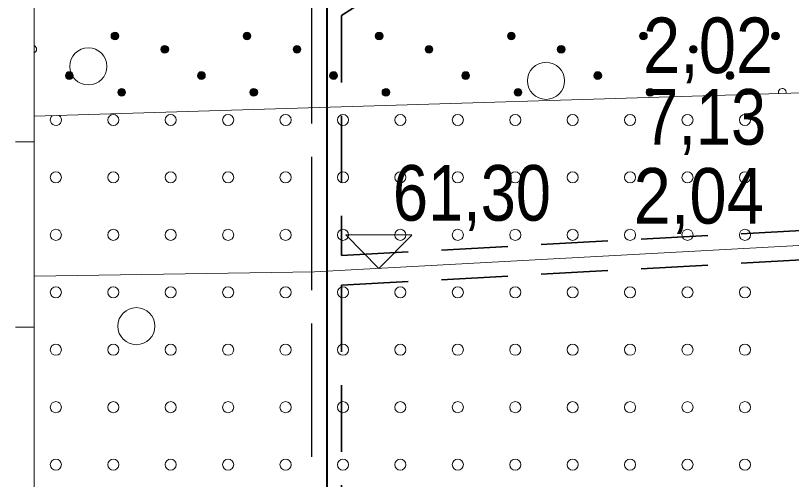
# Model space of a CAD drawing. Extents: x 640121 to 640955, y 6441885 to 6442246.
# Drawn here: x 640159.01 to 640200.9, y 6441940.19 to 6441965.23 of the extents above; entities that cross this region are included whole.
import ezdxf
from ezdxf.enums import TextEntityAlignment as Align

# ---------------------------------------------------------------- set-up
doc = ezdxf.new("R2010")
doc.units = 0
doc.header["$LTSCALE"] = 1.2
doc.linetypes.add('LONG_DASHED', pattern=[7.5, 6, -1.5])
doc.linetypes.add('MEDIUM_DASHED', pattern=[4.5, 3, -1.5])
for name, color, linetype, lineweight in [('30', 7, 'Continuous', 13), ('31', 7, 'Continuous', 13), ('32', 7, 'Continuous', 13), ('34', 7, 'Continuous', 25), ('35', 7, 'Continuous', 35), ('43', 7, 'Continuous', 13), ('44', 7, 'Continuous', 13), ('47', 7, 'Continuous', 13)]:
    doc.layers.add(name, color=color, linetype=linetype, lineweight=lineweight)

msp = doc.modelspace()

# ---------------------------------------------------------------- hatches: boundary and pattern name
at = {"layer": '44'}
for points in [[(640164.586, 6441964.122, 1), (640164.166, 6441964.122, 1)], [(640171.719, 6441964.122, 1), (640171.299, 6441964.122, 1)], [(640178.852, 6441964.122, 1), (640178.432, 6441964.122, 1)], [(640185.985, 6441964.122, 1), (640185.565, 6441964.122, 1)], [(640193.118, 6441964.122, 1), (640192.698, 6441964.122, 1)], [(640200.251, 6441964.122, 1), (640199.831, 6441964.122, 1)], [(640167.279, 6441963.406, 1), (640166.859, 6441963.406, 1)], [(640174.412, 6441963.406, 1), (640173.992, 6441963.406, 1)], [(640181.545, 6441963.406, 1), (640181.125, 6441963.406, 1)], [(640188.678, 6441963.406, 1), (640188.258, 6441963.406, 1)], [(640195.811, 6441963.406, 1), (640195.391, 6441963.406, 1)], [(640162.123, 6441961.987, 1), (640161.703, 6441961.987, 1)], [(640169.256, 6441961.987, 1), (640168.836, 6441961.987, 1)], [(640176.389, 6441961.987, 1), (640175.969, 6441961.987, 1)], [(640183.522, 6441961.987, 1), (640183.102, 6441961.987, 1)], [(640190.655, 6441961.987, 1), (640190.235, 6441961.987, 1)], [(640197.788, 6441961.987, 1), (640197.368, 6441961.987, 1)], [(640164.95, 6441961.079, 1), (640164.53, 6441961.079, 1)], [(640172.083, 6441961.079, 1), (640171.663, 6441961.079, 1)], [(640179.216, 6441961.079, 1), (640178.796, 6441961.079, 1)], [(640186.349, 6441961.079, 1), (640185.929, 6441961.079, 1)], [(640193.482, 6441961.079, 1), (640193.062, 6441961.079, 1)]]:
    msp.add_hatch(color=256, dxfattribs=at).paths.add_polyline_path(points)

# ---------------------------------------------------------------- linework, layer by layer
at = {"layer": '30'}
for p, q in [((640160.01, 6441898.41), (640160.01, 6442028.41)), ((640159.01, 6441958.41), (640160.01, 6441958.41)), ((640159.01, 6441948.41), (640160.01, 6441948.41))]:
    msp.add_line(p, q, dxfattribs=at)
at = {"layer": '31'}
msp.add_lwpolyline([(640160.01, 6441959.79), (640212.12, 6441961.38), (640223.03, 6441962.4), (640231.14, 6441963.16), (640235.45, 6441963.66), (640242.38, 6441964.64), (640247.49, 6441965.44), (640252.3, 6441966.45), (640254.5, 6441966.85), (640259.39, 6441967.38), (640264.58, 6441967.44), (640269.06, 6441967.32)], dxfattribs=at)
at = {"layer": '32', "linetype": 'LONG_DASHED', "lineweight": 25}
msp.add_line((640175.01, 6441914.41), (640175.01, 6441969.45), dxfattribs=at)
at = {"layer": '34', "lineweight": 13}
msp.add_lwpolyline([(640160.01, 6441951.16), (640175.15, 6441951.4), (640211.9, 6441953.4), (640235.85, 6441954.52), (640281.21, 6441954.51), (640334.24, 6441954.41), (640399.04, 6441956.94), (640444.67, 6441958.31), (640465.01, 6441958.56)], dxfattribs=at)
at = {"layer": '34'}
msp.add_lwpolyline([(640176.84, 6441953.39), (640178.63, 6441951.57), (640180.4, 6441953.38)], close=True, dxfattribs=at)
at = {"layer": '35', "lineweight": 40}
msp.add_line((640175.81, 6441965.88), (640175.81, 6441915.21), dxfattribs=at)
at = {"layer": '35', "linetype": 'MEDIUM_DASHED'}
for p, q in [((640176.61, 6441965.22), (640176.61, 6441952.28)), ((640176.61, 6441950.68), (640176.61, 6441916.01))]:
    msp.add_line(p, q, dxfattribs=at)
for points in [[(640176.61, 6441965.22), (640179.6, 6441967.21), (640183.42, 6441970.88), (640185.17, 6441972.59), (640186.87, 6441974.49), (640189.62, 6441977.53), (640192.74, 6441981.9), (640195.31, 6441986.36), (640197.15, 6441989.55), (640198.02, 6441991.61), (640198.93, 6441993.44), (640199.85, 6441995.72), (640201.01, 6441998.1), (640202.64, 6442001.88), (640204.34, 6442005.56), (640205.04, 6442007.41)], [(640176.61, 6441952.28), (640211.86, 6441954.2), (640235.83, 6441955.32), (640272.41, 6441955.31)], [(640176.61, 6441950.68), (640211.95, 6441952.61), (640235.86, 6441953.72), (640272.41, 6441953.71)]]:
    msp.add_lwpolyline(points, dxfattribs=at)
at = {"layer": '43'}
for centre in [(640164.288, 6441959.593), (640167.388, 6441959.593), (640170.488, 6441959.593), (640173.588, 6441959.593), (640176.688, 6441959.593), (640179.788, 6441959.593), (640182.888, 6441959.593), (640185.988, 6441959.593), (640189.088, 6441959.593), (640192.188, 6441959.593), (640195.288, 6441959.593), (640198.388, 6441959.593), (640161.188, 6441956.493), (640164.288, 6441956.493), (640167.388, 6441956.493), (640170.488, 6441956.493), (640173.588, 6441956.493), (640176.688, 6441956.493), (640179.788, 6441956.493), (640182.888, 6441956.493), (640185.988, 6441956.493), (640189.088, 6441956.493), (640192.188, 6441956.493), (640195.288, 6441956.493), (640198.388, 6441956.493), (640161.188, 6441953.393), (640164.288, 6441953.393), (640167.388, 6441953.393), (640170.488, 6441953.393), (640173.588, 6441953.393), (640176.688, 6441953.393), (640179.788, 6441953.393), (640182.888, 6441953.393), (640185.988, 6441953.393), (640189.088, 6441953.393), (640192.188, 6441953.393), (640195.288, 6441953.393), (640198.388, 6441953.393), (640161.188, 6441950.293), (640164.288, 6441950.293), (640167.388, 6441950.293), (640170.488, 6441950.293), (640173.588, 6441950.293), (640176.688, 6441950.293), (640179.788, 6441950.293), (640182.888, 6441950.293), (640185.988, 6441950.293), (640189.088, 6441950.293), (640192.188, 6441950.293), (640195.288, 6441950.293), (640198.388, 6441950.293), (640161.188, 6441947.193), (640164.288, 6441947.193), (640167.388, 6441947.193), (640170.488, 6441947.193), (640173.588, 6441947.193), (640176.688, 6441947.193), (640179.788, 6441947.193), (640182.888, 6441947.193), (640185.988, 6441947.193), (640189.088, 6441947.193), (640192.188, 6441947.193), (640195.288, 6441947.193), (640198.388, 6441947.193), (640161.188, 6441944.093), (640164.288, 6441944.093), (640167.388, 6441944.093), (640170.488, 6441944.093), (640173.588, 6441944.093), (640176.688, 6441944.093), (640179.788, 6441944.093), (640182.888, 6441944.093), (640185.988, 6441944.093), (640189.088, 6441944.093), (640192.188, 6441944.093), (640195.288, 6441944.093), (640198.388, 6441944.093), (640161.188, 6441940.993), (640164.288, 6441940.993), (640167.388, 6441940.993), (640170.488, 6441940.993), (640173.588, 6441940.993), (640176.688, 6441940.993), (640179.788, 6441940.993), (640182.888, 6441940.993), (640185.988, 6441940.993), (640189.088, 6441940.993), (640192.188, 6441940.993), (640195.288, 6441940.993), (640198.388, 6441940.993)]:
    msp.add_circle(centre, 0.3, dxfattribs=at)
msp.add_arc((640161.188, 6441959.593), 0.3, 129.9687, 53.5272, dxfattribs=at)
at = {"layer": '44'}
for centre in [(640164.376, 6441964.122), (640171.509, 6441964.122), (640178.642, 6441964.122), (640185.775, 6441964.122), (640192.908, 6441964.122), (640200.041, 6441964.122), (640167.069, 6441963.406), (640174.202, 6441963.406), (640181.335, 6441963.406), (640188.468, 6441963.406), (640195.601, 6441963.406), (640161.913, 6441961.987), (640169.046, 6441961.987), (640176.179, 6441961.987), (640183.312, 6441961.987), (640190.445, 6441961.987), (640197.578, 6441961.987), (640164.74, 6441961.079), (640171.873, 6441961.079), (640179.006, 6441961.079), (640186.139, 6441961.079), (640193.272, 6441961.079)]:
    msp.add_circle(centre, 0.21, dxfattribs=at)
for centre, start, end in [((640159.936, 6441963.406), 290.924, 69.076), ((640200.405, 6441961.079), 346.9113, 196.5845)]:
    msp.add_arc(centre, 0.21, start, end, dxfattribs=at)
at = {"layer": '47'}
for centre in [(640162.941, 6441962.483), (640187.649, 6441961.703), (640165.534, 6441948.466)]:
    msp.add_circle(centre, 1, dxfattribs=at)

# ---------------------------------------------------------------- texts
at = {"layer": '32'}
for s, width, p in [('2,02', 0.9, (640196.4, 6441962.12)), ('7,13', 0.85, (640196.215, 6441958.26)), ('2,04', 0.9, (640195.895, 6441954))]:
    msp.add_text(s, height=3, dxfattribs=dict(at, width=width)).set_placement(p, align=Align.CENTER)
at = {"layer": '34', "width": 0.85}
msp.add_text('61,30', height=3, dxfattribs=at).set_placement((640183.65, 6441954.16), align=Align.CENTER)

doc.saveas('drawing.dxf')
